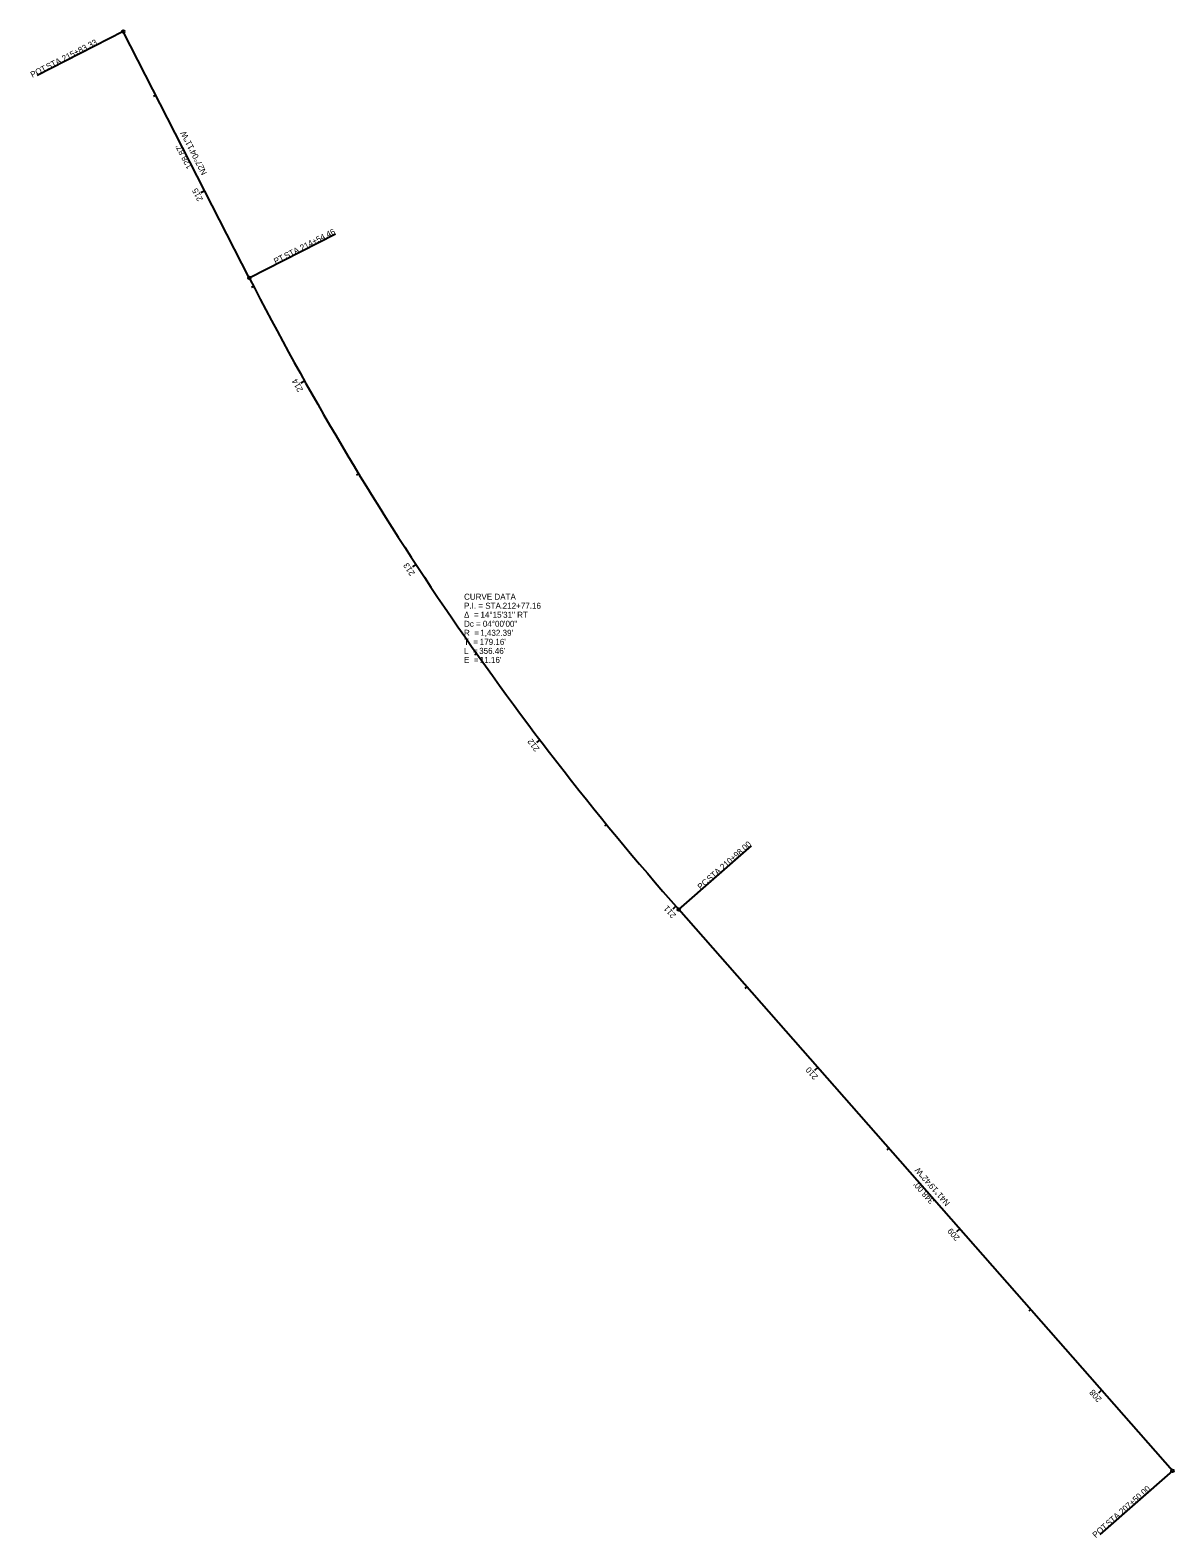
# Model space of a CAD drawing. Extents: x 186757 to 187290, y 351988 to 352690.
import ezdxf

# ---------------------------------------------------------------- set-up
doc = ezdxf.new("R2010")
doc.units = 0
for name, color, linetype in [('GE_X_Alignment', 7, 'Continuous'), ('GE_X_Alignment_100_Bearings', 7, 'Continuous'), ('GE_X_Alignment_100_Cardinal_Points', 7, 'Continuous'), ('GE_X_Alignment_100_Curve_Data', 7, 'Continuous'), ('GE_X_Alignment_100_Distances', 7, 'Continuous'), ('GE_X_Alignment_100_Stations', 7, 'Continuous')]:
    doc.layers.add(name, color=color, linetype=linetype)

msp = doc.modelspace()

# ---------------------------------------------------------------- linework, layer by layer
at = {"layer": 'GE_X_Alignment'}
for p, q in [((186859.37, 352574.99), (186800.73, 352689.74)), ((187289.02, 352019.59), (187059.21, 352280.92))]:
    msp.add_line(p, q, dxfattribs=at)
msp.add_arc((188134.85, 353226.83), 1432.39, 207.06959, 221.3282, dxfattribs=at)
at = {"layer": 'GE_X_Alignment_100_Cardinal_Points'}
for p, q in [((186800.73, 352689.74), (186760.66, 352669.26)), ((186859.37, 352574.99), (186899.44, 352595.46)), ((187059.21, 352280.92), (187093, 352310.63)), ((187289.02, 352019.59), (187255.23, 351989.87))]:
    msp.add_line(p, q, dxfattribs=at)
for centre in [(186800.73, 352689.74), (186859.37, 352574.99), (187059.21, 352280.92), (187289.02, 352019.59)]:
    msp.add_circle(centre, 0.6, dxfattribs=at)
at = {"layer": 'GE_X_Alignment_100_Stations'}
for p, q in [((186815.9, 352660.06), (186814.83, 352659.51)), ((186838.65, 352615.53), (186836.87, 352614.62)), ((186861.41, 352571.01), (186860.34, 352570.46)), ((186885.07, 352526.97), (186883.33, 352525.99)), ((186910.26, 352483.78), (186909.23, 352483.16)), ((186936.94, 352441.5), (186935.26, 352440.4)), ((186965.07, 352400.17), (186964.09, 352399.47)), ((186994.64, 352359.85), (186993.04, 352358.64)), ((187025.59, 352320.58), (187024.66, 352319.82)), ((187057.89, 352282.42), (187056.39, 352281.1)), ((187090.91, 352244.87), (187090.01, 352244.08)), ((187123.93, 352207.33), (187122.43, 352206)), ((187156.95, 352169.78), (187156.05, 352168.99)), ((187189.96, 352132.23), (187188.46, 352130.91)), ((187222.98, 352094.68), (187222.08, 352093.89)), ((187256, 352057.14), (187254.5, 352055.82)), ((187289.02, 352019.59), (187288.12, 352018.8))]:
    msp.add_line(p, q, dxfattribs=at)

# ---------------------------------------------------------------- texts
at = {"layer": 'GE_X_Alignment_100_Bearings'}
for s, rotation, p in [('N27°04\'11"W', 117.06959, (186839.8, 352623.83)), ('N41°19\'42"W', 131.3282, (187185.67, 352144.39))]:
    msp.add_text(s, height=2.8, rotation=rotation, dxfattribs=at).set_placement(p)
at = {"layer": 'GE_X_Alignment_100_Cardinal_Points'}
for s, rotation, p in [('215+83.33', 27.06959, (186773.03, 352675.63)), (' STA. ', 27.06959, (186764.73, 352671.39)), ('POT', 27.06959, (186758.38, 352668.14)), ('214+54.46', 27.06959, (186883.82, 352587.52)), ('PT', 27.06959, (186871.64, 352581.3)), (' STA. ', 27.06959, (186875.52, 352583.28)), ('210+98.00', 41.3282, (187079.9, 352299.16)), (' STA. ', 41.3282, (187072.9, 352293.01)), ('PC', 41.3282, (187069.45, 352289.97)), ('207+50.00', 41.3282, (187265.61, 351999.05)), ('POT', 41.3282, (187253.25, 351988.18)), (' STA. ', 41.3282, (187258.6, 351992.89))]:
    msp.add_text(s, height=2.8, rotation=rotation, dxfattribs=at).set_placement(p)
at = {"layer": 'GE_X_Alignment_100_Curve_Data'}
for s, p in [('CURVE DATA', (186959.29, 352425.15)), ('P.I. = STA. ', (186959.29, 352420.95)), ('212+77.16', (186977.28, 352420.95)), ('Δ  = ', (186959.29, 352416.75)), ('Dc = ', (186959.29, 352412.55)), ('14°15\'31" RT', (186966.94, 352416.75)), ('04°00\'00"', (186968.04, 352412.55)), ('R  = ', (186959.29, 352408.35)), ("1,432.39'", (186966.83, 352408.35)), ('T  = ', (186959.29, 352404.15)), ('L  = ', (186959.29, 352399.95)), ("356.46'", (186966.33, 352399.95)), ("179.16'", (186966.61, 352404.15)), ('E  = ', (186959.29, 352395.75)), ("11.16'", (186966.63, 352395.75))]:
    msp.add_text(s, height=2.8, dxfattribs=at).set_placement(p)
at = {"layer": 'GE_X_Alignment_100_Distances'}
for s, rotation, p in [("128.87'", 117.06959, (186832.95, 352626.61)), ("348.00'", 131.3282, (187178.34, 352145.4))]:
    msp.add_text(s, height=2.8, rotation=rotation, dxfattribs=at).set_placement(p)
at = {"layer": 'GE_X_Alignment_100_Stations'}
for s, rotation, p in [('215', 117.06959, (186837.88, 352611.54)), ('214', 119.24817, (186884.49, 352522.89)), ('213', 123.24818, (186936.6, 352437.45)), ('212', 127.24819, (186994.59, 352355.78)), ('211', 131.2482, (187058.14, 352278.35)), ('210', 131.3282, (187124.21, 352203.22)), ('209', 131.3282, (187190.22, 352128.16)), ('208', 131.3282, (187256.27, 352053.05))]:
    msp.add_text(s, height=2.8, rotation=rotation, dxfattribs=at).set_placement(p)

doc.saveas('drawing.dxf')
